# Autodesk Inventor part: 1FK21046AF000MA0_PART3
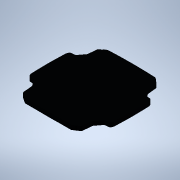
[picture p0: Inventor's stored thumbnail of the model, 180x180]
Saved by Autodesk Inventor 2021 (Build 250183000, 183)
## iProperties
Created: 2025-04
Part Number: 1FK21046AF000MA0_PART3
Material: Generic
Catalog Web Link: www.3dfindit.com
Description: -Servo synchronous motor
Document SubType Name: Modeling
Designer: psAdmin
Mass: 21.7019 g
Surface Area: 120.085 cm^2
Volume: 21.7019 cm^3
Density: 1 g/cm^3
Appearance: PSOLRGB-38-46-56
Category: PARTsolutions
Title: 1FK21046AF000MA0_PART3
Author: Cadenas PARTsolutions
Comments: Servo synchronous motor
Sending System: PARTsolutions
Preprocessor: ST-DEVELOPER v19.3
PSOL_IDENT_0: {$CADENAS_DATA/23d-libs/siemens_ag/_cat_/1c/1f/1fk21046af000ma0.prj},213 {VTYP=3D},{NB=1FK21046AF000
PSOL_IDENT_1: MA0_PART3},{LINA=1FK21046AF000MA0_PART3},{NN=1FK21046AF000MA0_PART3},{NOPRJ=TRUE},{DATE=19.08.2025 1
PSOL_IDENT_2: 4:00:28},{GEOMDATE=30.07.2025 02:02:08},{VERSION=},{LINEID=10},{WBVAR=},{WBNUMERIC=}  {NB=1FK21046AF
PSOL_IDENT_3: 000MA0_PART3},{LINA=1FK21046AF000MA0_PART3},{KT=DUMMY},{PREVIEW=../../../_pool_/cb/72/p_d211_xx_0043
PSOL_IDENT_4: 4j.png},{DESCSHORT=SIMOTICS S-1FK2 HD, SINAMICS S210 3AC 400V-480V, 3.2 Nm, 3000 rpm},{DESCLONG=SIMO
PSOL_IDENT_5: TICS S-1FK2 HD servo motor M0=3.2 Nm; PN = 1 kW at nN=3000 rpm (380-480 V); PN = 0.5 kW at nN=1500 r
PSOL_IDENT_6: pm (200-240 V); degree of protection IP64; cylindrical shaft D19x40mm; absolute encoder 22-bit + 12-
PSOL_IDENT_7: bit multiturn (encoder AM22DQC); with OCC interface; plug size M17, rotatable; SIMOTICS S-1FK2 servo
PSOL_IDENT_8: motorfor a wide range of uses in industrial environments. SIMOTICS S‑1FK2 servomotors are compact sy
PSOL_IDENT_9: nchronous motors with a high dynamic performance that set themselves apart as a result of their high
PSOL_IDENT_10: power density, degree of protection and overload capability. The motors are available in two varian
PSOL_IDENT_11: ts: as High Dynamic variant (highest dynamic performance as a result of the low intrinsic moment of
PSOL_IDENT_12: inertia for applications demanding a high dynamic performance with low moved masses) - and as Compac
PSOL_IDENT_13: t variant (precise and stable closed-loop control for medium up to large moved masses as a result of
PSOL_IDENT_14: a medium intrinsic moment of inertia). SIMOTICSS‑1FK2 servomotors fully exploit their strengths in
PSOL_IDENT_15: a system with the SINAMICSS210 frequency converter and simple connection using the one cable connect
PSOL_IDENT_16: ion (OCC). Advantages include the short control and positioning times, fast and precise correction o
PSOL_IDENT_17: f disturbing quantities as well as stable control with a high dynamic performance. The servo motors
PSOL_IDENT_18: can be configured to address a wide range of requirements. For example with and without holding brak
PSOL_IDENT_19: e, IP64 or IP65 degree of protection, singleturn or multiturn absolute encoders - to name just a few
PSOL_IDENT_20: . Further, the servomotors are available in different shaft heights extending from 20 to 100. A shaf
PSOL_IDENT_21: t sealing ring is available to achieve an IP65 degree of protection and for subsequent mounting at t
PSOL_IDENT_22: he motor or as spare part. SIMOTICS - the optimum motor for each and every motion control applicatio
PSOL_IDENT_23: n.},{INTNO=195125049666},{SUPPLIERALTNO=1FK2104-6AF00-0MA0},{MANUID=1FK21046AF000MA0},{MANUNAME=Siem
PSOL_IDENT_24: ens},{MANUTYPEDESC=Synchronous motor 1FK2-HD 3.2 NM},{AAU732=SIMOTICS},{AAO057=S-1FK2},{AAU734=SIMOT
PSOL_IDENT_25: ICS S-1FK2 HD servo motor M0=3.2 Nm; PN = 1 kW at nN=3000 rpm (380-480 V); PN = 0.5 kW at nN=1500 rp
PSOL_IDENT_26: m (200-240 V); degree of protection IP64; cylindrical shaft D19x40mm; absolute encoder 22-bit + 12-b
PSOL_IDENT_27: it multiturn (encoder AM22DQC); with OCC interface; plug size M17, rotatable;},{AAW338=Synchronous m
PSOL_IDENT_28: otor 1FK2-HD 3.2 NM},{AAO742=SIMOTICS},{AAO663=4042948694374},{NOCUPEROU=1},{PRICEQUANTITY=1},{QUANT
PSOL_IDENT_29: ITYMIN=1},{QUANTITYINT=1},{CTN=85015220},{COO=DE},{AAO676=1FK2104-6AF00-0MA0},{AAO677=Siemens AG},{O
PSOL_IDENT_30: RDERUNIT=C62},{CONTENTUNIT=C62}
NB: 1FK21046AF000MA0_PART3
NT: Servo synchronous motor
NBSYN: $MANUID._PART3
LINA: 1FK21046AF000MA0_PART3
CATALOG: SIEMENS
PREVIEW: ../../../_pool_/cb/72/p_d211_xx_00434j.png
DESCSHORT: SIMOTICS S-1FK2 HD, SINAMICS S210 3AC 400V-480V, 3.2 Nm, 3000 rpm
DESCLONG: SIMOTICS S-1FK2 HD servo motor M0=3.2 Nm; PN = 1 kW at nN=3000 rpm (380-480 V); PN = 0.5 kW at nN=1500 rpm (200-240 V); degree of protection IP64; cylindrical s
INTNO: 195125049666
SUPPLIERALTNO: 1FK2104-6AF00-0MA0
MANUID: 1FK21046AF000MA0
MANUNAME: Siemens
MANUTYPEDESC: Synchronous motor 1FK2-HD 3.2 NM
AAU732: SIMOTICS
AAO057: S-1FK2
AAU734: SIMOTICS S-1FK2 HD servo motor M0=3.2 Nm; PN = 1 kW at nN=3000 rpm (380-480 V); PN = 0.5 kW at nN=1500 rpm (200-240 V); degree of protection IP64; cylindrical s
AAW338: Synchronous motor 1FK2-HD 3.2 NM
AAO742: SIMOTICS
AAO663: 4042948694374.0
NOCUPEROU: 1
PRICEQUANTITY: 1
QUANTITYMIN: 1
QUANTITYINT: 1
CTN: 85015220
COO: DE
ARTICLENO: 1FK21046AF000MA0_PART3
BOMINFO: 1FK21046AF000MA0_PART3
CREATOR: CADENAS GmbH
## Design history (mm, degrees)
feature "2025_04_17_15_39_11_0331"
body "Solid1"
